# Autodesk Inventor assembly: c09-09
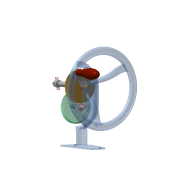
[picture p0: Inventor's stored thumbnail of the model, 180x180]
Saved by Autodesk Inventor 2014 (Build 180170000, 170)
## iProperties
Created: 2010-12
Part Number: c09-09
Document SubType Name: Assembly
Designer: Thom Tremblay
Author: Thom Tremblay
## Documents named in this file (12)
- C:\Inventor 2014 Essentials\Assemblies\Chapter 09\c09-09.iam
- C:\Inventor 2014 Essentials\Content Center Files\en-US\ISO 2795  F\ISO 2795 - 10 x 14 x 10F.ipt
- C:\Inventor 2014 Essentials\Content Center Files\en-US\ISO 4032\ISO 4032 - M12ISO.ipt
- C:\Inventor 2014 Essentials\Parts\Chapter 09\c09-04.ipt
- C:\Inventor 2014 Essentials\Parts\Chapter 09\c09-05.ipt
- C:\Inventor 2014 Essentials\Assemblies\Chapter 09\Design Accelerators\Shaft c09-01.iam
- C:\Inventor 2014 Essentials\Assemblies\Chapter 09\Design Accelerators\Shaft c09-02.iam
- C:\Inventor 2014 Essentials\Assemblies\Chapter 09\Design Accelerators\Cut Gear c09-01.iam
- C:\Inventor 2014 Essentials\Assemblies\Chapter 09\Design Accelerators\Cut Gear c09-02.iam
- C:\Inventor 2014 Essentials\Assemblies\Chapter 09\Design Accelerators\Spur Gear c09-01.iam
- C:\Inventor 2014 Essentials\Parts\Chapter 09\c09-11.ipt
- C:\Inventor 2014 Essentials\Assemblies\Chapter 09\Design Accelerators\Shaft c09-07.iam
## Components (12 placed, 9 different names)
1. c09-11:1 — Insert:1, Insert:2, Drive this Constraint
2. c09-04:1 — Insert:3, Mate:2, Mate:3, Angle:3
3. c09-05:1 — Insert:3
4. ISO 2795 (Flanged) 10 x 14 x 10:2 — Insert:2, Insert:6
5. ISO 2795 (Flanged) 10 x 14 x 10:3 — Insert:1, Insert:4
6. ISO 4032 M12:1 — Insert:7, Angle:1, Mate:4, Mate:5
7. Input Shaft [sub-assembly] — Insert:4, Mate:1, Mate:2, Mate:3, Angle:3
8. Output Shaft:2 [sub-assembly] — Insert:7, Mate:1, Flush:1, Angle:1, Rotation:1
9. Cut Gear:1 [sub-assembly]
10. Cut Gear:2 [sub-assembly]
11. Cut Gear:3 [sub-assembly] — Insert:5, Flush:1, Angle:2
12. New Shaft:1 [sub-assembly] — Insert:5, Insert:6, Angle:2, Rotation:1, Drive this Constraint
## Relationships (18: Insert 7, Mate 5, Angle 4, Flush 1, RelateRotation 1)
- Insert:1: c09-11:1 ↔ ISO 2795 (Flanged) 10 x 14 x 10:3
- Insert:2: c09-11:1 ↔ ISO 2795 (Flanged) 10 x 14 x 10:2
- Insert:3: c09-04:1 ↔ c09-05:1
- Insert:4: ISO 2795 (Flanged) 10 x 14 x 10:3 ↔ Input Shaft
- Insert:5: Cut Gear:3 ↔ New Shaft:1
- Insert:6: ISO 2795 (Flanged) 10 x 14 x 10:2 ↔ New Shaft:1
- Insert:7: ISO 4032 M12:1 ↔ Output Shaft:2
- Mate:1: Input Shaft ↔ Output Shaft:2
- Flush:1: Output Shaft:2 ↔ Cut Gear:3
- Angle:1: ISO 4032 M12:1 ↔ Output Shaft:2
- Angle:2: Cut Gear:3 ↔ New Shaft:1
- Mate:2: c09-04:1 ↔ Input Shaft
- Mate:3: c09-04:1 ↔ Input Shaft
- Angle:3: c09-04:1 ↔ Input Shaft
- Rotation:1 [RelateRotation]: Output Shaft:2 ↔ New Shaft:1
- Mate:4: ISO 4032 M12:1
- Mate:5: ISO 4032 M12:1
- Drive this Constraint [Angle]: c09-11:1 ↔ New Shaft:1
